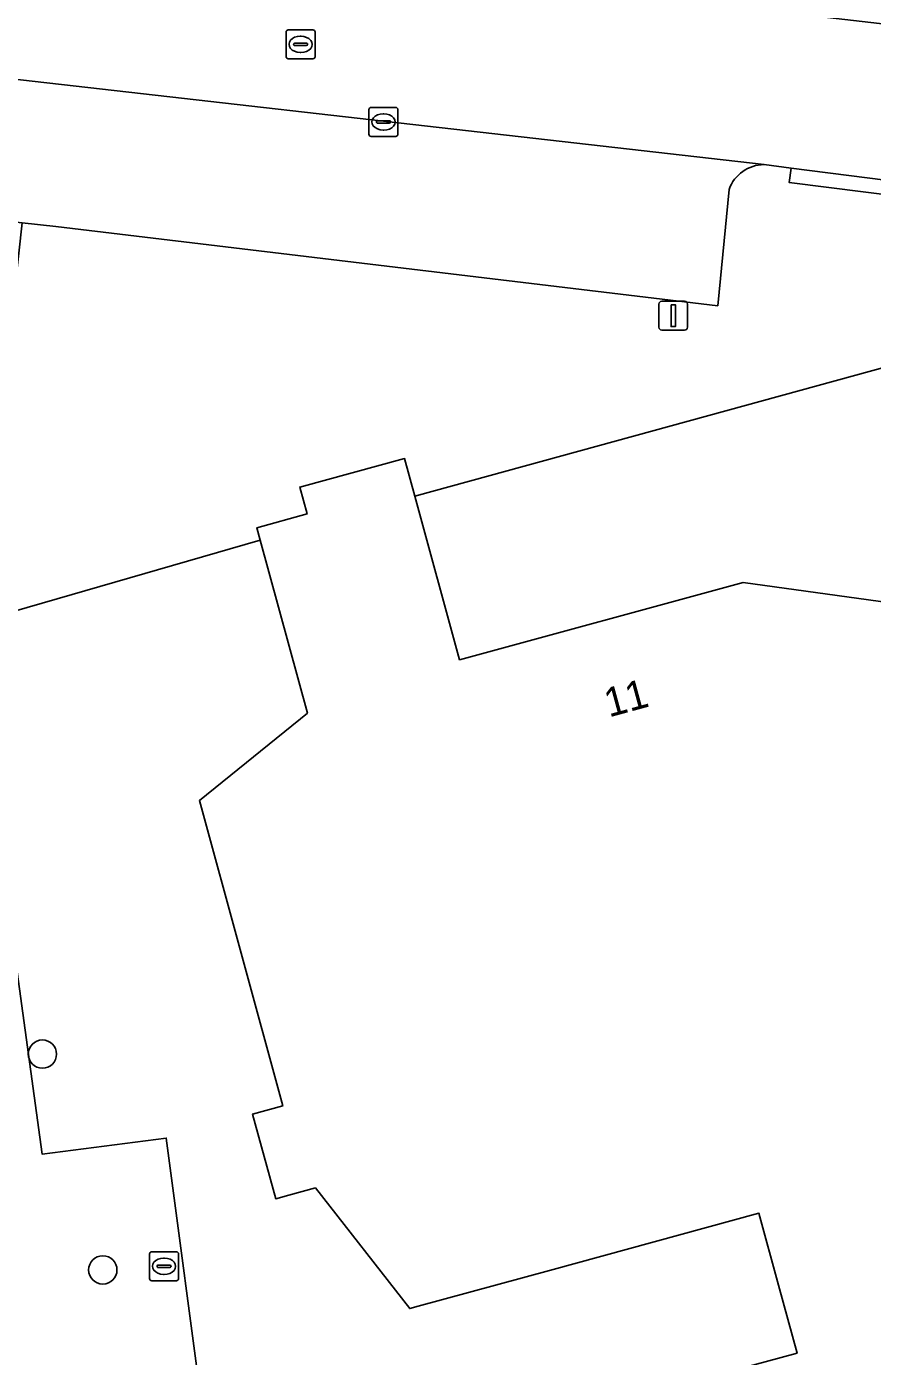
# Model space of a CAD drawing. Extents: x 162250 to 162661, y 380743 to 381606.
# Drawn here: x 162393.16 to 162422.34, y 381314.78 to 381360.68 of the extents above; entities that cross this region are included whole.
import ezdxf

# ---------------------------------------------------------------- set-up
doc = ezdxf.new("R2010")
doc.units = 0
for name, color, linetype in [('IMGEO_Boom', 7, 'Continuous'), ('IMGEO_Erf', 7, 'Continuous'), ('IMGEO_Kolk', 7, 'Continuous'), ('IMGEO_Lichtmast', 7, 'Continuous'), ('IMGEO_Pand', 7, 'Continuous'), ('IMGEO_Pand_nummerreeks', 7, 'Continuous'), ('IMGEO_Parkeervlak_open', 7, 'Continuous'), ('IMGEO_Rijbaan_lokaal_open', 7, 'Continuous'), ('IMGEO_Rioolput', 7, 'Continuous'), ('IMGEO_Voetpad_open', 7, 'Continuous'), ('IMGEO_Woonerf_open', 7, 'Continuous')]:
    doc.layers.add(name, color=color, linetype=linetype)

msp = doc.modelspace()

# ---------------------------------------------------------------- linework, layer by layer
at = {"layer": 'IMGEO_Boom'}
for centre in [(162393.704, 381325.214), (162395.788, 381317.766)]:
    msp.add_circle(centre, 0.489, dxfattribs=at)
at = {"layer": 'IMGEO_Erf'}
for points in [[(162426.714, 381350.004), (162406.556, 381344.473), (162408.097, 381338.824), (162417.882, 381341.494), (162423.284, 381340.745)], [(162415.034, 381313.611), (162419.742, 381314.897), (162419.101, 381317.243), (162418.425, 381319.72), (162411.204, 381317.749), (162406.67, 381316.511), (162406.38, 381316.432), (162403.121, 381320.596), (162402.205, 381320.346), (162401.753, 381320.223), (162400.957, 381323.142), (162401.997, 381323.426), (162399.121, 381333.962), (162402.848, 381336.985), (162401.22, 381342.95), (162391.181, 381340.053), (162393.692, 381321.762), (162397.974, 381322.315), (162399.277, 381312.558)]]:
    msp.add_lwpolyline(points, dxfattribs=at)
at = {"layer": 'IMGEO_Kolk'}
for p, q in [((162404.971, 381356.96), (162404.971, 381357.812)), ((162405.046, 381357.886), (162405.898, 381357.886)), ((162405.972, 381357.812), (162405.972, 381356.96)), ((162405.23, 381357.38), (162405.23, 381357.392)), ((162405.668, 381357.343), (162405.27, 381357.343)), ((162405.273, 381357.429), (162405.671, 381357.429)), ((162405.459, 381357.666), (162405.484, 381357.666)), ((162405.714, 381357.392), (162405.714, 381357.38)), ((162405.898, 381356.886), (162405.046, 381356.886)), ((162405.482, 381357.106), (162405.457, 381357.106))]:
    msp.add_line(p, q, dxfattribs=at)
for points in [[(162404.971, 381356.96), (162404.971, 381357.812)], [(162405.046, 381357.886), (162405.898, 381357.886)], [(162405.972, 381357.812), (162405.972, 381356.96)], [(162405.898, 381356.886), (162405.046, 381356.886)]]:
    msp.add_lwpolyline(points, dxfattribs=at)
for centre, radius, start, end in [((162405.048, 381357.81), 0.0765, 91.552, 178.448), ((162405.048, 381357.81), 0.0765, 91.552, 178.448), ((162405.896, 381357.81), 0.0765, 1.552, 88.448), ((162405.896, 381357.81), 0.0765, 1.552, 88.448), ((162405.27, 381357.389), 0.0403, 85.8775, 175.7526), ((162405.267, 381357.379), 0.0366, 178.938, 274.7102), ((162405.671, 381357.386), 0.043, 264.8664, 352.4533), ((162405.675, 381357.391), 0.0386, 1.7309, 96.639), ((162405.048, 381356.962), 0.0765, 181.552, 268.448), ((162405.048, 381356.962), 0.0765, 181.552, 268.448), ((162405.896, 381356.962), 0.0765, 271.552, 358.448), ((162405.896, 381356.962), 0.0765, 271.552, 358.448)]:
    msp.add_arc(centre, radius, start, end, dxfattribs=at)
for centre, major_axis, ratio, start_param, end_param in [((162405.458, 381357.386), (-0.387, 0.002), 0.722429, 4.712389, 7.853982), ((162405.483, 381357.386), (-0.39, 0.002), 0.717154, 1.570796, 4.712389)]:
    msp.add_ellipse(centre, major_axis=major_axis, ratio=ratio, start_param=start_param, end_param=end_param, dxfattribs=at)
at = {"layer": 'IMGEO_Lichtmast'}
for p, q in [((162414.974, 381350.301), (162414.974, 381351.101)), ((162414.974, 381351.101), (162414.974, 381350.301)), ((162415.074, 381351.201), (162415.864, 381351.201)), ((162415.864, 381351.201), (162415.074, 381351.201)), ((162415.964, 381351.101), (162415.964, 381350.301)), ((162415.964, 381350.301), (162415.964, 381351.101)), ((162415.864, 381350.201), (162415.074, 381350.201)), ((162415.074, 381350.201), (162415.864, 381350.201))]:
    msp.add_line(p, q, dxfattribs=at)
msp.add_lwpolyline([(162415.394, 381351.076), (162415.544, 381351.076), (162415.544, 381350.326), (162415.394, 381350.326), (162415.394, 381351.076)], dxfattribs=at)
for centre, start, end in [((162415.074, 381351.101), 90, 180), ((162415.074, 381351.101), 90, 180), ((162415.864, 381351.101), 0, 90), ((162415.864, 381351.101), 360, 90), ((162415.074, 381350.301), 180, 270), ((162415.074, 381350.301), 180, 270), ((162415.864, 381350.301), 270, 0), ((162415.864, 381350.301), 270, 0)]:
    msp.add_arc(centre, 0.1, start, end, dxfattribs=at)
at = {"layer": 'IMGEO_Pand'}
msp.add_lwpolyline([(162423.284, 381340.745), (162417.882, 381341.494), (162408.097, 381338.824), (162406.556, 381344.473), (162406.202, 381345.769), (162402.584, 381344.782), (162402.837, 381343.856), (162401.102, 381343.383), (162401.22, 381342.95), (162402.848, 381336.985), (162399.121, 381333.962), (162401.997, 381323.426), (162400.957, 381323.142), (162401.753, 381320.223), (162402.205, 381320.346), (162403.121, 381320.596), (162406.38, 381316.432), (162406.67, 381316.511), (162411.204, 381317.749), (162418.425, 381319.72), (162419.101, 381317.243), (162419.742, 381314.897), (162415.034, 381313.611)], dxfattribs=at)
at = {"layer": 'IMGEO_Parkeervlak_open'}
for points in [[(162418.607, 381355.915), (162385.463, 381359.688)], [(162386.212, 381358.601), (162385.776, 381354.729), (162393.006, 381353.91), (162394.167, 381353.778), (162417.008, 381351.045), (162417.398, 381355.06)]]:
    msp.add_lwpolyline(points, dxfattribs=at)
msp.add_arc((162418.614, 381354.623), 1.292, 90.3027, 160.2329, dxfattribs=at)
at = {"layer": 'IMGEO_Rijbaan_lokaal_open'}
msp.add_lwpolyline([(162424.469, 381360.557), (162422.583, 381360.789), (162418.002, 381361.308), (162417.694, 381361.338), (162411.638, 381361.926), (162406.463, 381362.533), (162397.581, 381363.589), (162393.586, 381364.052), (162384.577, 381365.095), (162382.82, 381365.298), (162382.211, 381360.04), (162385.318, 381359.705), (162385.463, 381359.688), (162418.607, 381355.915), (162419.535, 381355.796), (162424.79, 381355.126), (162430.909, 381355.898), (162436.919, 381358.12)], dxfattribs=at)
at = {"layer": 'IMGEO_Rioolput'}
for p, q in [((162402.113, 381359.639), (162402.113, 381360.491)), ((162402.188, 381360.565), (162403.04, 381360.565)), ((162403.114, 381360.491), (162403.114, 381359.639)), ((162402.372, 381360.059), (162402.372, 381360.071)), ((162402.81, 381360.022), (162402.412, 381360.022)), ((162402.415, 381360.108), (162402.813, 381360.108)), ((162402.601, 381360.345), (162402.626, 381360.345)), ((162402.856, 381360.071), (162402.856, 381360.059)), ((162403.04, 381359.565), (162402.188, 381359.565)), ((162402.624, 381359.785), (162402.599, 381359.785)), ((162397.399, 381317.464), (162397.399, 381318.316)), ((162397.474, 381318.39), (162398.326, 381318.39)), ((162398.4, 381318.316), (162398.4, 381317.464)), ((162397.658, 381317.884), (162397.658, 381317.896)), ((162398.096, 381317.847), (162397.698, 381317.847)), ((162397.701, 381317.933), (162398.099, 381317.933)), ((162397.887, 381318.17), (162397.912, 381318.17)), ((162398.142, 381317.896), (162398.142, 381317.884)), ((162398.326, 381317.39), (162397.474, 381317.39)), ((162397.91, 381317.61), (162397.885, 381317.61))]:
    msp.add_line(p, q, dxfattribs=at)
for points in [[(162402.113, 381359.639), (162402.113, 381360.491)], [(162402.188, 381360.565), (162403.04, 381360.565)], [(162403.114, 381360.491), (162403.114, 381359.639)], [(162403.04, 381359.565), (162402.188, 381359.565)], [(162397.399, 381317.464), (162397.399, 381318.316)], [(162397.474, 381318.39), (162398.326, 381318.39)], [(162398.4, 381318.316), (162398.4, 381317.464)], [(162398.326, 381317.39), (162397.474, 381317.39)]]:
    msp.add_lwpolyline(points, dxfattribs=at)
for centre, radius, start, end in [((162402.19, 381360.489), 0.0765, 91.552, 178.448), ((162402.19, 381360.489), 0.0765, 91.552, 178.448), ((162403.038, 381360.489), 0.0765, 1.552, 88.448), ((162403.038, 381360.489), 0.0765, 1.552, 88.448), ((162402.412, 381360.068), 0.0403, 85.8775, 175.7526), ((162402.409, 381360.058), 0.0366, 178.938, 274.7102), ((162402.813, 381360.065), 0.043, 264.8664, 352.4533), ((162402.817, 381360.07), 0.0386, 1.7309, 96.639), ((162402.19, 381359.641), 0.0765, 181.552, 268.448), ((162402.19, 381359.641), 0.0765, 181.552, 268.448), ((162403.038, 381359.641), 0.0765, 271.552, 358.448), ((162403.038, 381359.641), 0.0765, 271.552, 358.448), ((162397.476, 381318.314), 0.0765, 91.552, 178.448), ((162397.476, 381318.314), 0.0765, 91.552, 178.448), ((162398.324, 381318.314), 0.0765, 1.552, 88.448), ((162398.324, 381318.314), 0.0765, 1.552, 88.448), ((162397.698, 381317.893), 0.0403, 85.8775, 175.7526), ((162397.695, 381317.883), 0.0366, 178.938, 274.7102), ((162398.099, 381317.89), 0.043, 264.8664, 352.4533), ((162398.103, 381317.895), 0.0386, 1.7309, 96.639), ((162397.476, 381317.466), 0.0765, 181.552, 268.448), ((162397.476, 381317.466), 0.0765, 181.552, 268.448), ((162398.324, 381317.466), 0.0765, 271.552, 358.448), ((162398.324, 381317.466), 0.0765, 271.552, 358.448)]:
    msp.add_arc(centre, radius, start, end, dxfattribs=at)
for centre, major_axis, ratio, start_param, end_param in [((162402.6, 381360.065), (-0.387, 0.002), 0.722429, 4.712389, 7.853982), ((162402.625, 381360.065), (-0.39, 0.002), 0.717154, 1.570796, 4.712389), ((162397.886, 381317.89), (-0.387, 0.002), 0.722429, 4.712389, 7.853982), ((162397.911, 381317.89), (-0.39, 0.002), 0.717154, 1.570796, 4.712389)]:
    msp.add_ellipse(centre, major_axis=major_axis, ratio=ratio, start_param=start_param, end_param=end_param, dxfattribs=at)
at = {"layer": 'IMGEO_Voetpad_open'}
for points in [[(162424.79, 381355.126), (162424.767, 381354.626), (162419.468, 381355.301), (162419.535, 381355.796), (162418.607, 381355.915)], [(162417.398, 381355.06), (162417.008, 381351.045), (162394.167, 381353.778), (162393.006, 381353.91), (162392.329, 381347.729), (162388.366, 381348.119), (162382.258, 381347.296), (162382.835, 381343.046), (162382.341, 381342.983), (162382.589, 381341.154), (162382.689, 381340.417), (162383.001, 381340.404), (162387.834, 381340.197), (162391.181, 381340.053), (162401.22, 381342.95), (162401.102, 381343.383), (162402.837, 381343.856), (162402.584, 381344.782), (162406.202, 381345.769), (162406.556, 381344.473), (162426.714, 381350.004)]]:
    msp.add_lwpolyline(points, dxfattribs=at)
msp.add_lwpolyline([(162424.79, 381355.126), (162419.535, 381355.796), (162419.468, 381355.301), (162424.767, 381354.626)], close=True, dxfattribs=at)
msp.add_arc((162418.614, 381354.623), 1.292, 90.3027, 160.2329, dxfattribs=at)
at = {"layer": 'IMGEO_Woonerf_open'}
msp.add_lwpolyline([(162399.277, 381312.558), (162397.974, 381322.315), (162393.692, 381321.762), (162391.181, 381340.053), (162387.834, 381340.197), (162388.94, 381331.411), (162389.278, 381328.726), (162390.659, 381318.82), (162385.978, 381318.253), (162384.732, 381328.004), (162384.364, 381330.734), (162383.001, 381340.404), (162382.689, 381340.417), (162378.223, 381339.752), (162375.227, 381339.335), (162379.939, 381305.421)], dxfattribs=at)

# ---------------------------------------------------------------- texts
at = {"layer": 'IMGEO_Pand_nummerreeks'}
msp.add_text('11', height=1, rotation=15.2626, dxfattribs=at).set_placement((162413.253, 381336.831))

doc.saveas('drawing.dxf')
